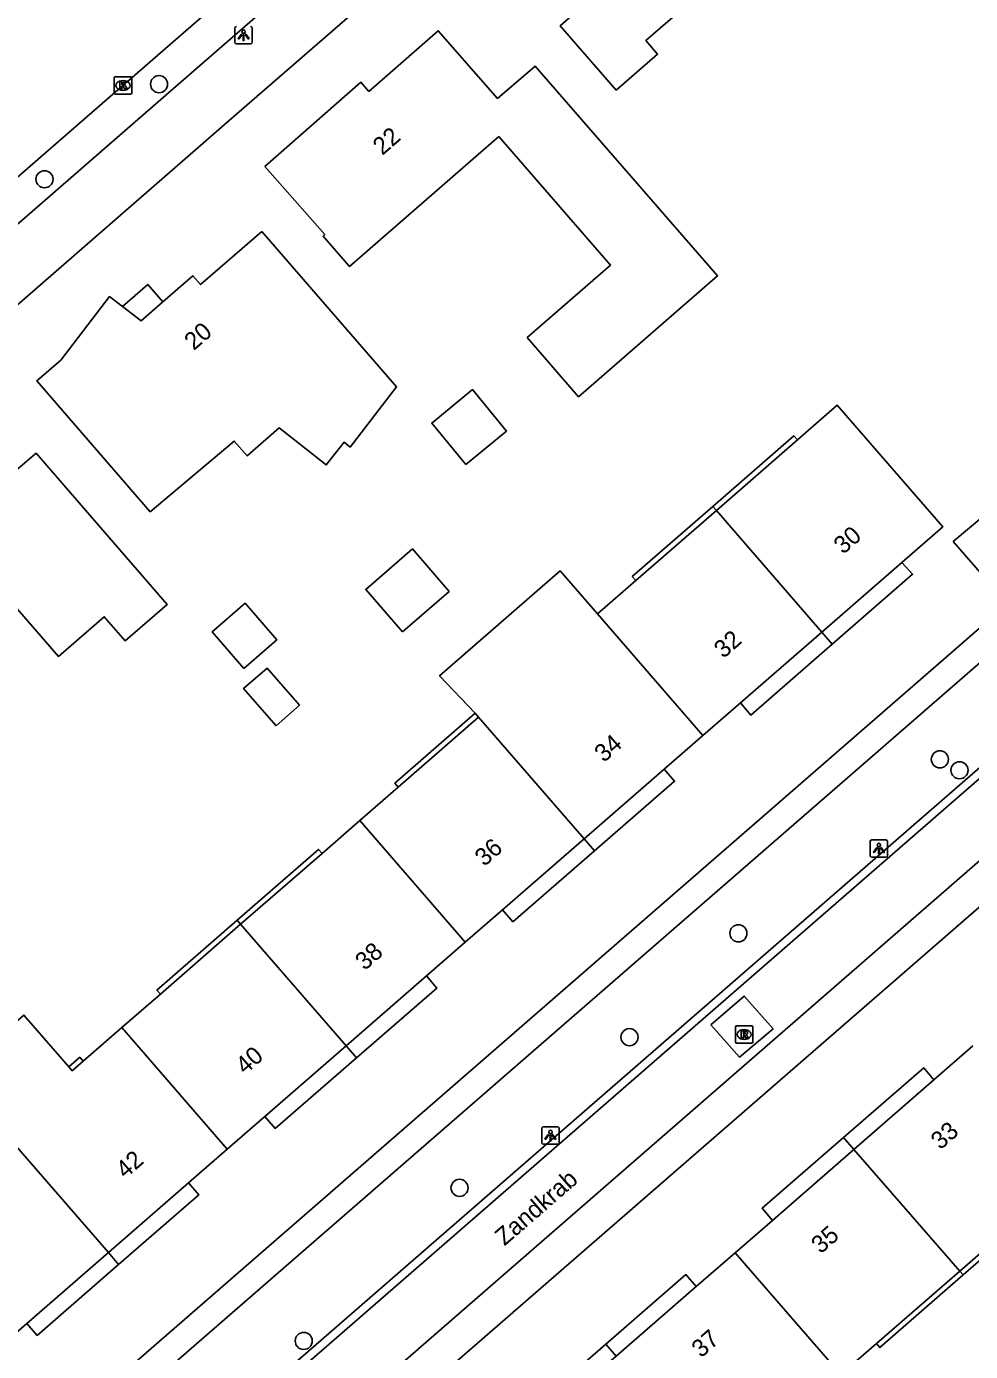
# Model space of a CAD drawing. Extents: x 155888 to 156864, y 383882 to 384671.
# Drawn here: x 156421 to 156475, y 384408.3 to 384483.9 of the extents above; entities that cross this region are included whole.
import ezdxf

# ---------------------------------------------------------------- set-up
doc = ezdxf.new("R2010")
doc.units = 0
for name, color, linetype in [('IMGEO_Boom', 7, 'Continuous'), ('IMGEO_Kolk', 7, 'Continuous'), ('IMGEO_Lichtpunt', 7, 'Continuous'), ('IMGEO_Openbare_ruimte_label', 7, 'Continuous'), ('IMGEO_Pand', 7, 'Continuous'), ('IMGEO_Pand_nummerreeks', 7, 'Continuous'), ('IMGEO_Pand_overbouw', 7, 'Continuous'), ('IMGEO_Rijbaan_lokaal_gesloten', 7, 'Continuous'), ('IMGEO_Rijbaan_lokaal_open', 7, 'Continuous'), ('IMGEO_Rioolput', 7, 'Continuous'), ('IMGEO_Voetpad_open', 7, 'Continuous')]:
    doc.layers.add(name, color=color, linetype=linetype)

msp = doc.modelspace()

# ---------------------------------------------------------------- linework, layer by layer
at = {"layer": 'IMGEO_Boom'}
for centre in [(156428.616, 384480.645), (156422.074, 384475.221), (156473.203, 384442.116), (156474.325, 384441.496), (156461.698, 384432.19), (156455.478, 384426.264), (156445.774, 384417.663), (156436.877, 384408.929)]:
    msp.add_circle(centre, 0.489, dxfattribs=at)
at = {"layer": 'IMGEO_Kolk'}
for p, q in [((156426.053, 384480.15), (156426.053, 384481.002)), ((156426.128, 384481.076), (156426.98, 384481.076)), ((156426.541, 384480.856), (156426.566, 384480.856)), ((156427.054, 384481.002), (156427.054, 384480.15)), ((156426.98, 384480.076), (156426.128, 384480.076)), ((156426.564, 384480.296), (156426.539, 384480.296))]:
    msp.add_line(p, q, dxfattribs=at)
for points in [[(156426.053, 384480.15), (156426.053, 384481.002)], [(156426.128, 384481.076), (156426.98, 384481.076)], [(156426.374, 384480.776), (156426.497, 384480.776), (156426.497, 384480.625), (156426.627, 384480.776), (156426.791, 384480.776), (156426.645, 384480.625), (156426.798, 384480.376), (156426.646, 384480.376), (156426.561, 384480.54), (156426.497, 384480.473), (156426.497, 384480.376), (156426.374, 384480.376), (156426.374, 384480.776)], [(156427.054, 384481.002), (156427.054, 384480.15)], [(156426.98, 384480.076), (156426.128, 384480.076)]]:
    msp.add_lwpolyline(points, dxfattribs=at)
for centre, start, end in [((156426.13, 384481), 91.55205, 178.44795), ((156426.13, 384481), 91.55205, 178.44795), ((156426.978, 384481), 1.55205, 88.44795), ((156426.978, 384481), 1.55205, 88.44795), ((156426.13, 384480.152), 181.55205, 268.44795), ((156426.13, 384480.152), 181.55205, 268.44795), ((156426.978, 384480.152), 271.55205, 358.44795), ((156426.978, 384480.152), 271.55205, 358.44795)]:
    msp.add_arc(centre, 0.0765, start, end, dxfattribs=at)
for centre, major_axis, ratio, start_param, end_param in [((156426.54, 384480.576), (-0.387, 0.002), 0.722429, 4.712389, 7.853982), ((156426.565, 384480.576), (-0.39, 0.002), 0.717154, 1.570796, 4.712389)]:
    msp.add_ellipse(centre, major_axis=major_axis, ratio=ratio, start_param=start_param, end_param=end_param, dxfattribs=at)
at = {"layer": 'IMGEO_Lichtpunt'}
for p, q in [((156432.941, 384483.844), (156432.941, 384483.037)), ((156432.941, 384483.844), (156432.941, 384483.037)), ((156433.937, 384483.037), (156433.937, 384483.844)), ((156433.937, 384483.037), (156433.937, 384483.844)), ((156433.035, 384482.943), (156433.843, 384482.943)), ((156433.035, 384482.943), (156433.843, 384482.943)), ((156469.222, 384437.429), (156469.222, 384436.622)), ((156469.222, 384437.429), (156469.222, 384436.622)), ((156470.124, 384437.524), (156469.316, 384437.524)), ((156470.124, 384437.524), (156469.316, 384437.524)), ((156470.218, 384436.622), (156470.218, 384437.429)), ((156470.218, 384436.622), (156470.218, 384437.429)), ((156469.316, 384436.528), (156470.124, 384436.528)), ((156469.316, 384436.528), (156470.124, 384436.528)), ((156450.465, 384421.053), (156450.465, 384420.246)), ((156450.465, 384421.053), (156450.465, 384420.246)), ((156451.367, 384421.148), (156450.559, 384421.148)), ((156451.367, 384421.148), (156450.559, 384421.148)), ((156451.461, 384420.246), (156451.461, 384421.053)), ((156451.461, 384420.246), (156451.461, 384421.053)), ((156450.559, 384420.152), (156451.367, 384420.152)), ((156450.559, 384420.152), (156451.367, 384420.152))]:
    msp.add_line(p, q, dxfattribs=at)
for points in [[(156433.315, 384483.508), (156433.354, 384483.48), (156433.166, 384483.218), (156433.128, 384483.245), (156433.315, 384483.508)], [(156433.417, 384483.46), (156433.464, 384483.46), (156433.464, 384483.138), (156433.417, 384483.138), (156433.417, 384483.46)], [(156433.527, 384483.48), (156433.565, 384483.507), (156433.752, 384483.245), (156433.713, 384483.217), (156433.527, 384483.48)], [(156469.596, 384437.093), (156469.635, 384437.065), (156469.447, 384436.803), (156469.409, 384436.83), (156469.596, 384437.093)], [(156469.698, 384437.045), (156469.745, 384437.045), (156469.745, 384436.723), (156469.698, 384436.723), (156469.698, 384437.045)], [(156469.808, 384437.065), (156469.846, 384437.092), (156470.033, 384436.83), (156469.994, 384436.802), (156469.808, 384437.065)], [(156450.839, 384420.717), (156450.878, 384420.689), (156450.69, 384420.427), (156450.652, 384420.454), (156450.839, 384420.717)], [(156450.941, 384420.669), (156450.988, 384420.669), (156450.988, 384420.347), (156450.941, 384420.347), (156450.941, 384420.669)], [(156451.051, 384420.689), (156451.089, 384420.716), (156451.276, 384420.454), (156451.237, 384420.426), (156451.051, 384420.689)]]:
    msp.add_lwpolyline(points, dxfattribs=at)
for centre in [(156433.44, 384483.642), (156469.721, 384437.227), (156450.964, 384420.851)]:
    msp.add_circle(centre, 0.0994, dxfattribs=at)
for centre, start, end in [((156433.035, 384483.844), 90, 180), ((156433.035, 384483.844), 90, 180), ((156433.843, 384483.844), 0, 90), ((156433.843, 384483.844), 0, 90), ((156433.035, 384483.037), 180, 270), ((156433.035, 384483.037), 180, 270), ((156433.843, 384483.037), 270, 0), ((156433.843, 384483.037), 270, 360), ((156469.316, 384437.429), 90, 180), ((156469.316, 384437.429), 90, 180), ((156470.124, 384437.429), 0, 90), ((156470.124, 384437.429), 0, 90), ((156469.316, 384436.622), 180, 270), ((156469.316, 384436.622), 180, 270), ((156470.124, 384436.622), 270, 0), ((156470.124, 384436.622), 270, 360), ((156450.559, 384421.053), 90, 180), ((156450.559, 384421.053), 90, 180), ((156451.367, 384421.053), 0, 90), ((156451.367, 384421.053), 0, 90), ((156450.559, 384420.246), 180, 270), ((156450.559, 384420.246), 180, 270), ((156451.367, 384420.246), 270, 0), ((156451.367, 384420.246), 270, 360)]:
    msp.add_arc(centre, 0.0946, start, end, dxfattribs=at)
at = {"layer": 'IMGEO_Pand'}
for points in [[(156454.713, 384480.309), (156457.081, 384482.366), (156456.413, 384483.135), (156461.284, 384487.366), (156463.799, 384484.471), (156468.188, 384488.283), (156462.69, 384494.594), (156460.074, 384492.274), (156457.7, 384495.004), (156449.494, 384487.855), (156452.285, 384484.643), (156451.523, 384483.981), (156454.713, 384480.309)], [(156449.626, 384466.189), (156452.566, 384462.808), (156460.495, 384469.709), (156450.09, 384481.683), (156447.944, 384479.837), (156444.559, 384483.696), (156440.598, 384480.234), (156440.139, 384480.76), (156434.655, 384475.946), (156438.074, 384472.067), (156437.976, 384471.982), (156439.485, 384470.246), (156448.01, 384477.658), (156453.757, 384471.048), (156454.384, 384470.326), (156449.626, 384466.189)], [(156434.481, 384472.231), (156430.973, 384469.214), (156430.542, 384469.715), (156428.835, 384468.227), (156427.588, 384467.14), (156426.52, 384467.963), (156425.79, 384468.525), (156422.996, 384464.898), (156421.635, 384463.72), (156428.11, 384456.247), (156432.909, 384460.283), (156433.636, 384459.444), (156435.472, 384461.036), (156438.159, 384458.918), (156439.178, 384460.211), (156439.523, 384459.939), (156442.167, 384463.368), (156434.481, 384472.231)], [(156446.128, 384458.945), (156448.453, 384460.855), (156446.51, 384463.218), (156444.186, 384461.308), (156446.128, 384458.945)], [(156466.459, 384449.38), (156471.032, 384453.354), (156473.371, 384455.387), (156467.341, 384462.322), (156465.068, 384460.347), (156460.437, 384456.321)], [(156413.577, 384445.494), (156414.331, 384446.149), (156414.62, 384445.817), (156420.398, 384450.838), (156422.875, 384447.986), (156425.485, 384450.254), (156426.684, 384448.874), (156429.083, 384450.958), (156421.59, 384459.589), (156418.053, 384456.578), (156416.369, 384458.556), (156415.608, 384457.909), (156415.33, 384458.236), (156413.8, 384456.905), (156413.367, 384457.402), (156409.892, 384454.38), (156410.325, 384453.882), (156408.78, 384452.538), (156409.062, 384452.214), (156408.308, 384451.558), (156413.577, 384445.494)], [(156480.439, 384453.92), (156477.468, 384457.472), (156473.969, 384454.547), (156477.069, 384450.993)], [(156460.437, 384456.321), (156455.833, 384452.32), (156453.648, 384450.421)], [(156466.459, 384449.38), (156460.437, 384456.321)], [(156442.518, 384449.394), (156445.179, 384451.706), (156443.08, 384454.123), (156440.418, 384451.811), (156442.518, 384449.394)], [(156446.859, 384444.52), (156446.662, 384444.747), (156444.63, 384446.886), (156451.518, 384452.872), (156453.648, 384450.421)], [(156433.452, 384447.311), (156435.334, 384448.946), (156433.528, 384451.024), (156431.646, 384449.389), (156433.452, 384447.311)], [(156453.648, 384450.421), (156459.671, 384443.479)], [(156459.671, 384443.479), (156461.808, 384445.337), (156466.459, 384449.38)], [(156435.292, 384444.038), (156436.631, 384445.202), (156434.782, 384447.33), (156433.443, 384446.167), (156435.292, 384444.038)], [(156446.859, 384444.52), (156442.266, 384440.528), (156440.071, 384438.619)], [(156452.882, 384437.578), (156446.859, 384444.52)], [(156459.671, 384443.479), (156457.454, 384441.553), (156452.882, 384437.578)], [(156440.071, 384438.619), (156437.923, 384436.753), (156433.274, 384432.712)], [(156446.092, 384431.677), (156440.071, 384438.619)], [(156446.092, 384431.677), (156448.233, 384433.538), (156452.882, 384437.578)], [(156433.274, 384432.712), (156428.688, 384428.726), (156426.485, 384426.811)], [(156433.274, 384432.712), (156439.296, 384425.77)], [(156439.296, 384425.77), (156443.886, 384429.76), (156446.092, 384431.677)], [(156426.485, 384426.811), (156424.278, 384424.893), (156423.652, 384424.349), (156423.456, 384424.576), (156420.898, 384427.52), (156416.935, 384424.076), (156419.499, 384421.137), (156419.696, 384420.911)], [(156432.507, 384419.869), (156426.485, 384426.811)], [(156432.507, 384419.869), (156434.656, 384421.737), (156439.296, 384425.77)], [(156468.296, 384419.857), (156472.864, 384423.827), (156475.089, 384425.762)], [(156425.718, 384413.968), (156419.696, 384420.911)], [(156425.718, 384413.968), (156430.3, 384417.951), (156432.507, 384419.869)], [(156461.507, 384413.956), (156463.635, 384415.806), (156468.296, 384419.857)], [(156474.338, 384412.919), (156468.296, 384419.857)], [(156481.127, 384418.82), (156478.807, 384416.803), (156474.338, 384412.919)], [(156418.721, 384407.887), (156421.064, 384409.924), (156425.718, 384413.968)], [(156454.715, 384408.053), (156459.293, 384412.032), (156461.507, 384413.956)], [(156461.507, 384413.956), (156467.55, 384407.019)], [(156474.338, 384412.919), (156469.574, 384408.779), (156467.55, 384407.019)]]:
    msp.add_lwpolyline(points, dxfattribs=at)
at = {"layer": 'IMGEO_Pand_overbouw'}
for points in [[(156426.52, 384467.963), (156427.588, 384467.14), (156428.835, 384468.227), (156427.966, 384469.223)], [(156460.437, 384456.321), (156465.068, 384460.347), (156464.871, 384460.573), (156460.24, 384456.548)], [(156460.437, 384456.321), (156460.24, 384456.548), (156455.637, 384452.547), (156455.833, 384452.32)], [(156471.032, 384453.354), (156466.459, 384449.38), (156467.056, 384448.692), (156471.64, 384452.679)], [(156461.808, 384445.337), (156462.401, 384444.644), (156467.056, 384448.692), (156466.459, 384449.38)], [(156442.266, 384440.528), (156446.859, 384444.52), (156446.662, 384444.747), (156442.07, 384440.755)], [(156452.882, 384437.578), (156453.477, 384436.893), (156458.053, 384440.869), (156457.454, 384441.553)], [(156452.882, 384437.578), (156448.233, 384433.538), (156448.822, 384432.848), (156453.477, 384436.893)], [(156433.274, 384432.712), (156437.923, 384436.753), (156437.726, 384436.979), (156433.077, 384432.939)], [(156433.274, 384432.712), (156433.077, 384432.939), (156428.492, 384428.953), (156428.688, 384428.726)], [(156439.296, 384425.77), (156439.891, 384425.084), (156444.485, 384429.069), (156443.886, 384429.76)], [(156439.296, 384425.77), (156434.656, 384421.737), (156435.241, 384421.052), (156439.891, 384425.084)], [(156423.456, 384424.576), (156423.652, 384424.349), (156424.278, 384424.893), (156424.081, 384425.119)], [(156468.296, 384419.857), (156472.864, 384423.827), (156472.278, 384424.52), (156467.7, 384420.541)], [(156468.296, 384419.857), (156467.7, 384420.541), (156463.049, 384416.498), (156463.635, 384415.806)], [(156425.718, 384413.968), (156426.307, 384413.289), (156430.89, 384417.271), (156430.3, 384417.951)], [(156478.807, 384416.803), (156474.338, 384412.919), (156474.535, 384412.693), (156479.001, 384416.574)], [(156421.064, 384409.924), (156421.652, 384409.246), (156426.307, 384413.289), (156425.718, 384413.968)], [(156454.715, 384408.053), (156459.293, 384412.032), (156458.699, 384412.716), (156454.118, 384408.739)], [(156469.574, 384408.779), (156469.768, 384408.55), (156474.535, 384412.693), (156474.338, 384412.919)], [(156454.715, 384408.053), (156454.118, 384408.739), (156449.467, 384404.701), (156450.056, 384404.003)]]:
    msp.add_lwpolyline(points, close=True, dxfattribs=at)
at = {"layer": 'IMGEO_Rijbaan_lokaal_gesloten'}
for points in [[(156385.943, 384445.252), (156386.238, 384445.513), (156426.553, 384480.577), (156426.95, 384480.922), (156448.887, 384500), (156466.428, 384515.254), (156476.04, 384523.575), (156500, 384544.42), (156507.992, 384551.373), (156512.78, 384555.514), (156551.569, 384589.179), (156578.098, 384612.298), (156579.282, 384613.324)], [(156426.433, 384399.009), (156427.492, 384399.882), (156435.101, 384405.965), (156436.569, 384407.23), (156500, 384462.343), (156522.19, 384481.631), (156524.469, 384483.595), (156538.047, 384495.41), (156543.317, 384500), (156545.489, 384501.892), (156599.206, 384548.488), (156600.688, 384549.796), (156608.807, 384556.844), (156609.964, 384557.948), (156616.394, 384563.892), (156618.279, 384565.679)], [(156429.337, 384395.556), (156437.726, 384403.475), (156439.179, 384404.792), (156499.799, 384457.474)]]:
    msp.add_lwpolyline(points, dxfattribs=at)
at = {"layer": 'IMGEO_Rijbaan_lokaal_open'}
for points in [[(156521.889, 384481.979), (156500, 384462.952), (156436.281, 384407.589), (156434.814, 384406.324), (156427.202, 384400.239), (156426.126, 384399.352)], [(156460.126, 384426.969), (156462.027, 384428.606), (156463.675, 384426.742), (156461.766, 384425.116), (156460.126, 384426.969)]]:
    msp.add_lwpolyline(points, dxfattribs=at)
at = {"layer": 'IMGEO_Rioolput'}
for p, q in [((156461.524, 384425.992), (156461.524, 384426.844)), ((156461.599, 384426.918), (156462.451, 384426.918)), ((156462.012, 384426.698), (156462.037, 384426.698)), ((156462.525, 384426.844), (156462.525, 384425.992)), ((156462.451, 384425.918), (156461.599, 384425.918)), ((156462.035, 384426.138), (156462.01, 384426.138))]:
    msp.add_line(p, q, dxfattribs=at)
for points in [[(156461.524, 384425.992), (156461.524, 384426.844)], [(156461.599, 384426.918), (156462.451, 384426.918)], [(156462.113, 384426.616), (156461.861, 384426.618), (156461.861, 384426.218)], [(156461.861, 384426.218), (156461.985, 384426.218), (156461.985, 384426.38), (156461.996, 384426.38)], [(156462.039, 384426.537), (156461.985, 384426.537), (156461.985, 384426.456)], [(156461.985, 384426.456), (156462.037, 384426.456)], [(156462.043, 384426.351), (156462.114, 384426.218), (156462.254, 384426.218), (156462.189, 384426.344)], [(156462.525, 384426.844), (156462.525, 384425.992)], [(156462.451, 384425.918), (156461.599, 384425.918)]]:
    msp.add_lwpolyline(points, dxfattribs=at)
for centre, radius, start, end in [((156461.601, 384426.842), 0.0765, 91.55205, 178.44795), ((156461.601, 384426.842), 0.0765, 91.55205, 178.44795), ((156461.995, 384426.327), 0.0533, 26.02933, 88.69889), ((156462.021, 384426.645), 0.19, 274.7715, 282.96867), ((156462.045, 384426.441), 0.0964, 77.00612, 93.18647), ((156462.059, 384426.498), 0.0378, 276.66336, 79.67722), ((156462.112, 384426.506), 0.109, 350.36119, 89.41601), ((156462.11, 384426.506), 0.112, 277.58423, 350.98172), ((156462.094, 384426.291), 0.108, 29.51342, 73.79051), ((156462.449, 384426.842), 0.0765, 1.55205, 88.44795), ((156462.449, 384426.842), 0.0765, 1.55205, 88.44795), ((156461.601, 384425.994), 0.0765, 181.55205, 268.44795), ((156461.601, 384425.994), 0.0765, 181.55205, 268.44795), ((156462.449, 384425.994), 0.0765, 271.55205, 358.44795), ((156462.449, 384425.994), 0.0765, 271.55205, 358.44795)]:
    msp.add_arc(centre, radius, start, end, dxfattribs=at)
for centre, major_axis, ratio, start_param, end_param in [((156462.011, 384426.418), (-0.387, 0.002), 0.722429, 4.712389, 7.853982), ((156462.036, 384426.418), (-0.39, 0.002), 0.717154, 1.570796, 4.712389)]:
    msp.add_ellipse(centre, major_axis=major_axis, ratio=ratio, start_param=start_param, end_param=end_param, dxfattribs=at)
at = {"layer": 'IMGEO_Voetpad_open'}
for points in [[(156387.279, 384443.752), (156428.273, 384479.396), (156451.969, 384500), (156477.412, 384522.142), (156500, 384541.752), (156509.198, 384549.738), (156578.017, 384609.497), (156582.526, 384613.433)], [(156389.717, 384441.255), (156430.543, 384476.776), (156432.323, 384478.325), (156457.305, 384500), (156479.838, 384519.516), (156485.227, 384524.21)], [(156426.126, 384399.352), (156423.484, 384402.425), (156426.371, 384404.961), (156500, 384468.928), (156518.931, 384485.374), (156521.889, 384481.979)], [(156477.069, 384450.993), (156422.469, 384403.554)], [(156490.462, 384446.708), (156485.017, 384441.983), (156484.867, 384441.853), (156430.348, 384394.521)]]:
    msp.add_lwpolyline(points, dxfattribs=at)

# ---------------------------------------------------------------- texts
at = {"layer": 'IMGEO_Openbare_ruimte_label'}
msp.add_text('Zandkrab', height=1, rotation=40.98653, dxfattribs=at).set_placement((156448.34, 384414.32))
at = {"layer": 'IMGEO_Pand_nummerreeks'}
for s, rotation, p in [('22', 41.15556, (156441.367, 384476.55)), ('20', 41.08107, (156430.599, 384465.414)), ('30', 40.99611, (156467.68, 384453.781)), ('32', 40.99611, (156460.845, 384447.84)), ('34', 40.99513, (156454.015, 384441.904)), ('36', 40.99611, (156447.184, 384435.967)), ('38', 40.99611, (156440.355, 384430.031)), ('40', 40.99611, (156433.524, 384424.094)), ('33', 40.9966, (156473.228, 384419.8)), ('42', 40.99611, (156426.688, 384418.152)), ('35', 40.9966, (156466.398, 384413.863)), ('37', 40.9966, (156459.568, 384407.926))]:
    msp.add_text(s, height=1, rotation=rotation, dxfattribs=at).set_placement(p)

doc.saveas('drawing.dxf')
